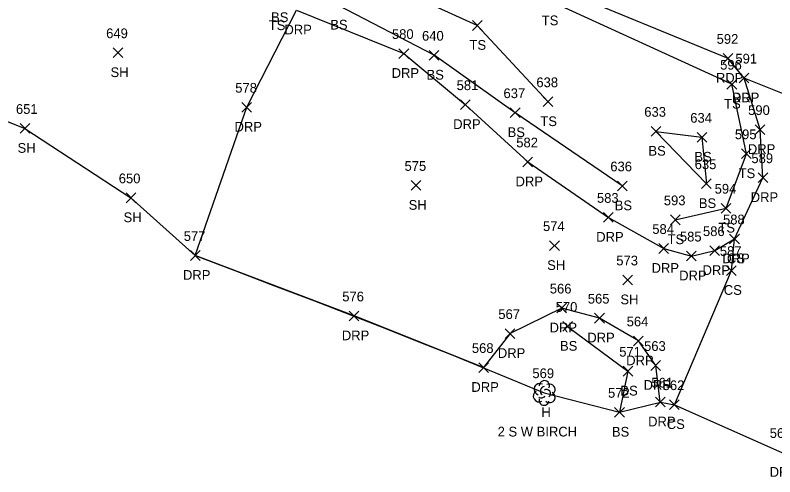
# Model space of a CAD drawing. Extents: x 1599569 to 1610055, y 642560 to 647860.
# Drawn here: x 1602887.6 to 1603043.9, y 647266.4 to 647361.4 of the extents above; entities that cross this region are included whole.
import ezdxf

# ---------------------------------------------------------------- set-up
doc = ezdxf.new("R2010")
doc.units = 0
for name, color, linetype in [('L_A', 7, 'Continuous'), ('L_C', 7, 'Continuous'), ('L_I', 7, 'Continuous'), ('L_TIC', 7, 'Continuous'), ('LELB', 7, 'Continuous'), ('LSOGP', 7, 'Continuous'), ('LTD', 7, 'Continuous'), ('P_A', 7, 'Continuous'), ('P_I', 7, 'Continuous'), ('P_TIC', 7, 'Continuous'), ('PET', 7, 'Continuous'), ('R_A', 7, 'Continuous'), ('R_I', 7, 'Continuous'), ('R_TIC', 7, 'Continuous'), ('RDP', 7, 'Continuous')]:
    doc.layers.add(name, color=color, linetype=linetype)

msp = doc.modelspace()

# ---------------------------------------------------------------- linework, layer by layer
at = {"layer": 'L_TIC'}
for points in [[(1602981.64, 647358.24), (1602983.64, 647360.24)], [(1602983.64, 647358.24), (1602981.64, 647360.24)], [(1602907.7, 647352.63), (1602909.7, 647354.63)], [(1602909.7, 647352.63), (1602907.7, 647354.63)], [(1602972.77, 647352.11), (1602974.77, 647354.11)], [(1602974.77, 647352.11), (1602972.77, 647354.11)], [(1603034.03, 647346.15), (1603036.03, 647348.15)], [(1603036.03, 647346.15), (1603034.03, 647348.15)], [(1602996.22, 647342.55), (1602998.22, 647344.55)], [(1602998.22, 647342.55), (1602996.22, 647344.55)], [(1602989.45, 647340.3), (1602991.45, 647342.3)], [(1602991.45, 647340.3), (1602989.45, 647342.3)], [(1602888.57, 647337.06), (1602890.57, 647339.06)], [(1602890.57, 647337.06), (1602888.57, 647339.06)], [(1603018.42, 647336.47), (1603020.42, 647338.47)], [(1603020.42, 647336.47), (1603018.42, 647338.47)], [(1603018.42, 647336.47), (1603020.42, 647338.47)], [(1603020.42, 647336.47), (1603018.42, 647338.47)], [(1603027.88, 647335.24), (1603029.88, 647337.24)], [(1603029.88, 647335.24), (1603027.88, 647337.24)], [(1603037.01, 647331.85), (1603039.01, 647333.85)], [(1603039.01, 647331.85), (1603037.01, 647333.85)], [(1602969.04, 647325.34), (1602971.04, 647327.34)], [(1602971.04, 647325.34), (1602969.04, 647327.34)], [(1603028.79, 647325.69), (1603030.79, 647327.69)], [(1603030.79, 647325.69), (1603028.79, 647327.69)], [(1603028.79, 647325.69), (1603030.79, 647327.69)], [(1603030.79, 647325.69), (1603028.79, 647327.69)], [(1603011.49, 647325.24), (1603013.49, 647327.24)], [(1603013.49, 647325.24), (1603011.49, 647327.24)], [(1602910.38, 647322.79), (1602912.38, 647324.79)], [(1602912.38, 647322.79), (1602910.38, 647324.79)], [(1603032.85, 647320.66), (1603034.85, 647322.66)], [(1603034.85, 647320.66), (1603032.85, 647322.66)], [(1603022.39, 647318.27), (1603024.39, 647320.27)], [(1603024.39, 647318.27), (1603022.39, 647320.27)], [(1602997.54, 647312.96), (1602999.54, 647314.96)], [(1602999.54, 647312.96), (1602997.54, 647314.96)], [(1603034.57, 647314.34), (1603036.57, 647316.34)], [(1603036.57, 647314.34), (1603034.57, 647316.34)], [(1603033.93, 647307.84), (1603035.93, 647309.84)], [(1603035.93, 647307.84), (1603033.93, 647309.84)], [(1603012.61, 647305.9), (1603014.61, 647307.9)], [(1603014.61, 647305.9), (1603012.61, 647307.9)], [(1603000.23, 647296.35), (1603002.23, 647298.35)], [(1603002.23, 647296.35), (1603000.23, 647298.35)], [(1603012.66, 647287.14), (1603014.66, 647289.14)], [(1603014.66, 647287.14), (1603012.66, 647289.14)], [(1603022.2, 647280.25), (1603024.2, 647282.25)], [(1603024.2, 647280.25), (1603022.2, 647282.25)], [(1603010.91, 647278.68), (1603012.91, 647280.68)], [(1603012.91, 647278.68), (1603010.91, 647280.68)]]:
    msp.add_lwpolyline(points, dxfattribs=at)
at = {"layer": 'LELB'}
for points in [[(1603012.49, 647326.24), (1602990.45, 647341.3), (1602973.77, 647353.11), (1602953.95, 647363.4), (1602916.83, 647376.34), (1602879.52, 647385.68), (1602861.45, 647391.05), (1602857.96, 647395.91), (1602856.57, 647396.23), (1602848.89, 647379.86), (1602843.21, 647377.7), (1602818.67, 647385.57), (1602771.25, 647404.63), (1602731.78, 647425.59), (1602689.48, 647442.33), (1602646.26, 647452.13), (1602605.47, 647460.82), (1602615.77, 647472.63), (1602617.29, 647479.52), (1602614.47, 647480.43), (1602602, 647462.58), (1602569.34, 647464.61)], [(1602997.22, 647343.55), (1602982.64, 647359.24), (1602956.26, 647371.23), (1602923.49, 647383.78), (1602881.48, 647394.49), (1602864.86, 647399.2), (1602857.7, 647404.45), (1602852.15, 647401.21), (1602844.53, 647381.78), (1602821.22, 647392.08), (1602783.51, 647427.85), (1602741.14, 647445.48), (1602700.04, 647463.04)], [(1603023.39, 647319.27), (1603033.85, 647321.66), (1603038.01, 647332.85), (1603035.03, 647347.15), (1602997.51, 647364.29), (1602957.03, 647381.25), (1602920.15, 647395.93), (1602878.36, 647413)], [(1603019.42, 647337.47), (1603028.88, 647336.24), (1603029.79, 647326.69)], [(1603019.42, 647337.47), (1603029.79, 647326.69)], [(1603023.2, 647281.25), (1603034.93, 647308.84), (1603035.57, 647315.34)], [(1603001.23, 647297.35), (1603013.66, 647288.14), (1603011.91, 647279.68)]]:
    msp.add_lwpolyline(points, dxfattribs=at)
at = {"layer": 'LSOGP'}
msp.add_lwpolyline([(1602865.6, 647347.66), (1602889.57, 647338.06), (1602911.38, 647323.79), (1602924.62, 647311.92), (1602932.79, 647308.82), (1602940.96, 647305.71), (1602949.13, 647302.61), (1602963.96, 647296.85), (1602970.62, 647294.2), (1602977.28, 647291.54), (1602996.4, 647283.71), (1603011.91, 647279.68), (1603020.32, 647281.78), (1603023.2, 647281.24), (1603045.32, 647271.42)], dxfattribs=at)
at = {"layer": 'LTD'}
msp.add_line((1602996.4, 647283.71), (1602996.4, 647283.71), dxfattribs=at)
msp.add_line((1602996.4, 647283.71), (1602996.4, 647283.71), dxfattribs=at)
msp.add_arc((1602996.45, 647285.15), 1.05, 335.5272, 180.9563, dxfattribs=at)
for centre, major_axis, ratio, start_param, end_param in [((1602995.61, 647284.38), (1.21, -0.51), 0.895232, 1.570796, 4.712389), ((1602997.44, 647284.29), (-1.14, -0.48), 0.949671, 1.570796, 4.712389), ((1602995.32, 647283), (0.58, -1.04), 0.959034, 3.141593, 6.283185), ((1602996.19, 647284.17), (-0.208, -0.792), 0.645439, 3.141593, 6.283185), ((1602996.9, 647283.54), (-0.5, 0.667), 0.989748, 3.141593, 6.283185), ((1602997.4, 647282.88), (-1.09, 0.79), 0.841452, 1.570796, 4.712389), ((1602996.4, 647282.21), (0.26, 1.06), 0.942809, 1.570796, 4.712389), ((1602995.94, 647282.96), (-0.625, -0.083), 0.423636, 0, 3.141593)]:
    msp.add_ellipse(centre, major_axis=major_axis, ratio=ratio, start_param=start_param, end_param=end_param, dxfattribs=at)
at = {"layer": 'P_TIC'}
for points in [[(1603033.26, 647351.47), (1603035.26, 647353.47)], [(1603035.26, 647351.47), (1603033.26, 647353.47)], [(1603036.55, 647347.42), (1603038.55, 647349.42)], [(1603038.55, 647347.42), (1603036.55, 647349.42)]]:
    msp.add_lwpolyline(points, dxfattribs=at)
at = {"layer": 'PET'}
msp.add_lwpolyline([(1603222.52, 647275.76), (1603183.61, 647291.56), (1603146.92, 647306.71), (1603109.5, 647322.06), (1603103.75, 647321.89), (1603092.3, 647325.95), (1603063.3, 647338.13), (1603037.55, 647348.42), (1603034.26, 647352.47), (1602998.81, 647367.08), (1602958.22, 647383.09), (1602921.43, 647398.55), (1602879.84, 647415.39)], dxfattribs=at)
at = {"layer": 'R_TIC'}
for points in [[(1602966.54, 647352.47), (1602968.54, 647354.47)], [(1602968.54, 647352.47), (1602966.54, 647354.47)], [(1603036.55, 647347.42), (1603038.55, 647349.42)], [(1603038.55, 647347.42), (1603036.55, 647349.42)], [(1602934.21, 647341.42), (1602936.21, 647343.42)], [(1602936.21, 647341.42), (1602934.21, 647343.42)], [(1602979.2, 647341.95), (1602981.2, 647343.95)], [(1602981.2, 647341.95), (1602979.2, 647343.95)], [(1603039.83, 647336.83), (1603041.83, 647338.83)], [(1603041.83, 647336.83), (1603039.83, 647338.83)], [(1602992.04, 647330.17), (1602994.04, 647332.17)], [(1602994.04, 647330.17), (1602992.04, 647332.17)], [(1603040.42, 647326.93), (1603042.42, 647328.93)], [(1603042.42, 647326.93), (1603040.42, 647328.93)], [(1603008.63, 647318.77), (1603010.63, 647320.77)], [(1603010.63, 647318.77), (1603008.63, 647320.77)], [(1603034.57, 647314.34), (1603036.57, 647316.34)], [(1603036.57, 647314.34), (1603034.57, 647316.34)], [(1603020.02, 647312.37), (1603022.02, 647314.37)], [(1603022.02, 647312.37), (1603020.02, 647314.37)], [(1603030.51, 647311.93), (1603032.51, 647313.93)], [(1603032.51, 647311.93), (1603030.51, 647313.93)], [(1602923.62, 647310.93), (1602925.62, 647312.93)], [(1602925.62, 647310.93), (1602923.62, 647312.93)], [(1603025.7, 647310.82), (1603027.7, 647312.82)], [(1603027.7, 647310.82), (1603025.7, 647312.82)], [(1602999.04, 647300.12), (1603001.04, 647302.12)], [(1603001.04, 647300.12), (1602999.04, 647302.12)], [(1602956.29, 647298.5), (1602958.29, 647300.5)], [(1602958.29, 647298.5), (1602956.29, 647300.5)], [(1603006.8, 647298.05), (1603008.8, 647300.05)], [(1603008.8, 647298.05), (1603006.8, 647300.05)], [(1602988.39, 647294.87), (1602990.39, 647296.87)], [(1602990.39, 647294.87), (1602988.39, 647296.87)], [(1603014.8, 647293.36), (1603016.8, 647295.36)], [(1603016.8, 647293.36), (1603014.8, 647295.36)], [(1602982.95, 647287.89), (1602984.95, 647289.89)], [(1602984.95, 647287.89), (1602982.95, 647289.89)], [(1603018.38, 647288.31), (1603020.38, 647290.31)], [(1603020.38, 647288.31), (1603018.38, 647290.31)], [(1603019.31, 647280.78), (1603021.31, 647282.78)], [(1603021.31, 647280.78), (1603019.31, 647282.78)]]:
    msp.add_lwpolyline(points, dxfattribs=at)
at = {"layer": 'RDP'}
msp.add_lwpolyline([(1603020.31, 647281.78), (1603019.38, 647289.31), (1603015.8, 647294.36), (1603007.8, 647299.05), (1603000.04, 647301.12), (1602989.39, 647295.87), (1602983.95, 647288.89), (1602957.29, 647299.5), (1602924.62, 647311.93), (1602935.21, 647342.42), (1602945.48, 647362.39), (1602967.54, 647353.47), (1602980.2, 647342.95), (1602993.04, 647331.17), (1603009.63, 647319.77), (1603021.02, 647313.37), (1603026.7, 647311.82), (1603031.51, 647312.93), (1603035.57, 647315.34), (1603041.42, 647327.93), (1603040.83, 647337.83), (1603037.55, 647348.42)], dxfattribs=at)

# ---------------------------------------------------------------- texts
at = {"layer": 'L_A'}
for s, p in [('BS', (1602940.22, 647359.94)), ('TS', (1602939.75, 647358.29)), ('BS', (1602952.4, 647358.4)), ('TS', (1602995.92, 647359.29)), ('TS', (1602981.05, 647354.24)), ('SH', (1602907.19, 647348.63)), ('BS', (1602972.21, 647348.11)), ('TS', (1603033.44, 647342.15)), ('TS', (1602995.63, 647338.55)), ('BS', (1602988.89, 647336.3)), ('SH', (1602888.06, 647333.06)), ('BS', (1603017.86, 647332.47)), ('BS', (1603017.86, 647332.47)), ('BS', (1603027.32, 647331.24)), ('TS', (1603036.42, 647327.85)), ('SH', (1602968.53, 647321.34)), ('BS', (1603010.93, 647321.24)), ('BS', (1603028.23, 647321.69)), ('BS', (1603028.23, 647321.69)), ('SH', (1602909.87, 647318.79)), ('TS', (1603032.26, 647316.66)), ('TS', (1603021.8, 647314.27)), ('CS', (1603034.01, 647310.34)), ('SH', (1602997.03, 647308.96)), ('CS', (1603033.37, 647303.84)), ('SH', (1603012.1, 647301.9)), ('BS', (1602999.67, 647292.35)), ('BS', (1603012.1, 647283.14)), ('H', (1602995.84, 647278.71)), ('CS', (1603021.64, 647276.25)), ('BS', (1603010.35, 647274.68))]:
    msp.add_text(s, height=2, dxfattribs=at).set_placement(p)
at = {"layer": 'L_C'}
msp.add_text('2 S W BIRCH', height=2, dxfattribs=at).set_placement((1602986.84, 647274.71))
at = {"layer": 'L_I'}
for s, p in [('649', (1602906.29, 647356.63)), ('640', (1602971.28, 647356.11)), ('596', (1603032.62, 647350.15)), ('638', (1602994.81, 647346.55)), ('637', (1602988.04, 647344.3)), ('651', (1602887.73, 647341.06)), ('633', (1603017.01, 647340.47)), ('633', (1603017.01, 647340.47)), ('634', (1603026.47, 647339.24)), ('595', (1603035.65, 647335.85)), ('575', (1602967.68, 647329.34)), ('636', (1603010.02, 647329.24)), ('635', (1603027.38, 647329.69)), ('635', (1603027.38, 647329.69)), ('650', (1602908.88, 647326.79)), ('594', (1603031.49, 647324.66)), ('593', (1603021.03, 647322.27)), ('588', (1603033.21, 647318.34)), ('574', (1602996.17, 647316.96)), ('587', (1603032.56, 647311.84)), ('573', (1603011.25, 647309.9)), ('570', (1602998.78, 647300.35)), ('571', (1603011.86, 647291.14)), ('569', (1602993.99, 647286.71)), ('562', (1603020.79, 647284.25)), ('572', (1603009.55, 647282.68))]:
    msp.add_text(s, height=2, dxfattribs=at).set_placement(p)
at = {"layer": 'P_A'}
for p in [(1603031.75, 647347.47), (1603035.04, 647343.42)]:
    msp.add_text('RDP', height=2, dxfattribs=at).set_placement(p)
at = {"layer": 'P_I'}
for s, p in [('592', (1603031.9, 647355.47)), ('591', (1603035.76, 647351.42))]:
    msp.add_text(s, height=2, dxfattribs=at).set_placement(p)
at = {"layer": 'R_A'}
for p in [(1602942.97, 647357.39), (1602965.03, 647348.47), (1603035.04, 647343.42), (1602977.69, 647337.95), (1602932.7, 647337.42), (1603038.32, 647332.83), (1602990.52, 647326.17), (1603038.91, 647322.93), (1603007.12, 647314.77), (1603033.06, 647310.34), (1603018.51, 647308.37), (1602922.1, 647306.93), (1603024.19, 647306.82), (1603029, 647307.93), (1602997.53, 647296.12), (1602954.78, 647294.5), (1603005.29, 647294.05), (1602986.88, 647290.87), (1603013.29, 647289.36), (1602981.44, 647283.89), (1603016.87, 647284.31), (1603017.8, 647276.78), (1603042.81, 647266.42)]:
    msp.add_text('DRP', height=2, dxfattribs=at).set_placement(p)
at = {"layer": 'R_I'}
for s, p in [('580', (1602965.09, 647356.47)), ('591', (1603035.76, 647351.42)), ('581', (1602978.4, 647345.95)), ('578', (1602932.85, 647345.42)), ('590', (1603038.38, 647340.83)), ('582', (1602990.67, 647334.17)), ('589', (1603039.05, 647330.93)), ('583', (1603007.27, 647322.77)), ('588', (1603033.21, 647318.34)), ('584', (1603018.66, 647316.37)), ('586', (1603029.09, 647315.93)), ('577', (1602922.25, 647314.93)), ('585', (1603024.34, 647314.82)), ('566', (1602997.57, 647304.12)), ('576', (1602954.87, 647302.5)), ('565', (1603005.39, 647302.05)), ('567', (1602986.98, 647298.87)), ('564', (1603013.39, 647297.36)), ('568', (1602981.54, 647291.89)), ('563', (1603016.97, 647292.31)), ('561', (1603018.47, 647284.78)), ('560', (1603042.82, 647274.42))]:
    msp.add_text(s, height=2, dxfattribs=at).set_placement(p)

doc.saveas('drawing.dxf')
